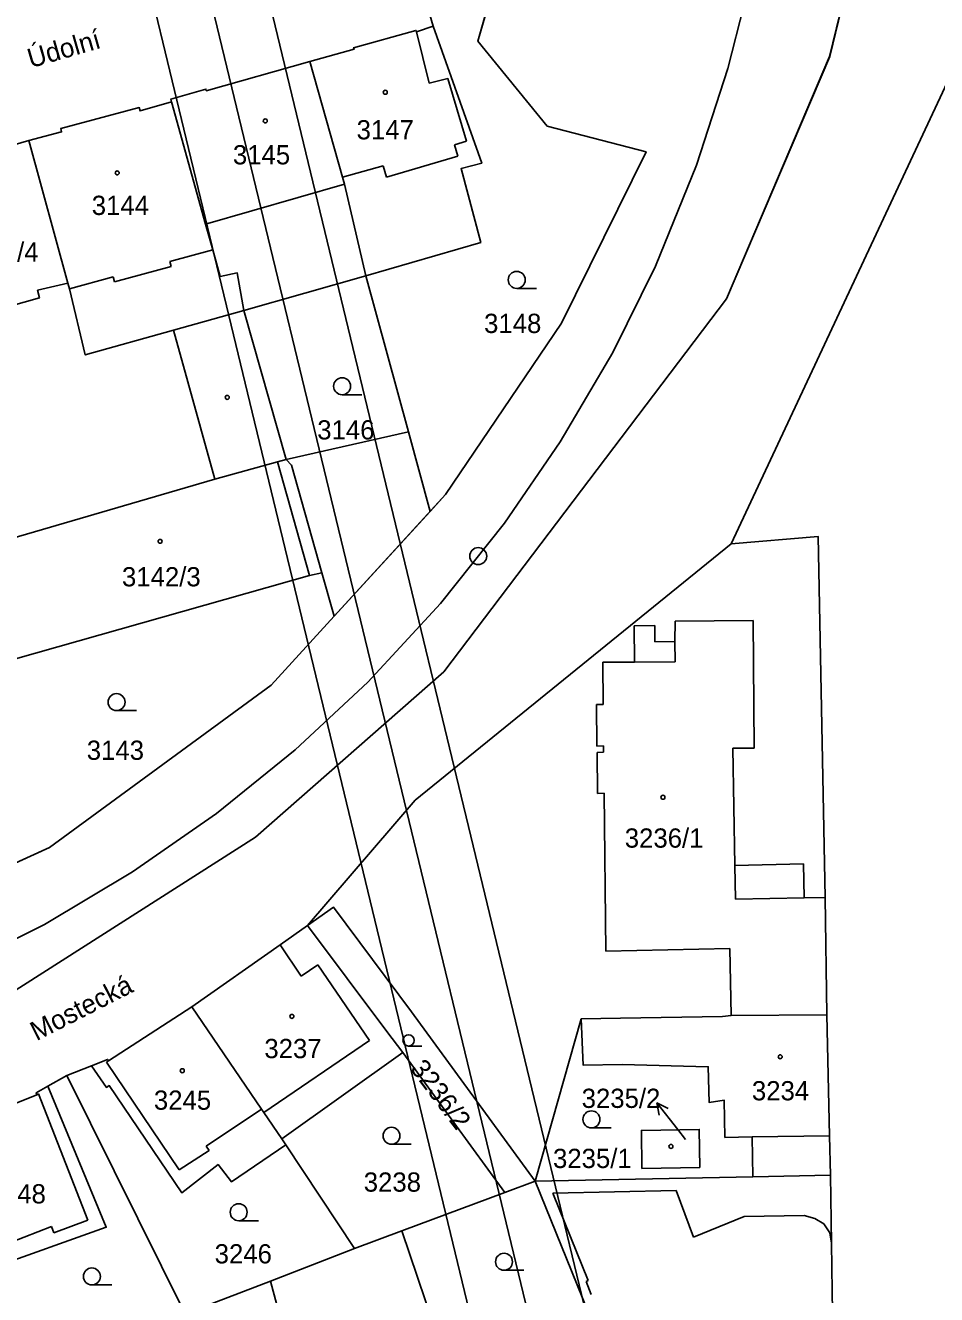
# Model space of a CAD drawing. Extents: x -738085 to -734306, y -1122197 to -1119753.
# Drawn here: x -734521 to -734440.5, y -1120242.7 to -1120130.5 of the extents above; entities that cross this region are included whole.
import ezdxf

# ---------------------------------------------------------------- set-up
doc = ezdxf.new("R2010")
doc.units = 0
for name, color, linetype in [('Hranice parcel', 7, 'Continuous'), ('Parcelní čísla', 7, 'Continuous'), ('Pop  PČ popisy', 7, 'Continuous'), ('SŽDC', 7, 'Continuous'), ('Vnitřní kresba', 7, 'Continuous'), ('Vrstva 1', 7, 'Continuous'), ('Vrstva 53', 7, 'Continuous'), ('Vrstva 7', 7, 'Continuous'), ('Značky budov', 7, 'Continuous'), ('Značky kultur', 7, 'Continuous')]:
    doc.layers.add(name, color=color, linetype=linetype)

msp = doc.modelspace()

# ---------------------------------------------------------------- linework, layer by layer
at = {"layer": 'Hranice parcel'}
for p, q in [((-734439.36, -1120135.08), (-734458.68, -1120176.34)), ((-734530.15, -1120143.44), (-734520.74, -1120140.71)), ((-734520.74, -1120140.71), (-734517.27, -1120153.31)), ((-734501.73, -1120155.71), (-734490.95, -1120152.67)), ((-734493.74, -1120182.73), (-734485.26, -1120173.47)), ((-734493.74, -1120182.73), (-734494.83, -1120178.89)), ((-734471.92, -1120218.33), (-734475.99, -1120232.66)), ((-734498.39, -1120228.91), (-734487.7, -1120221.3)), ((-734487.7, -1120221.3), (-734478.67, -1120233.66)), ((-734515.18, -1120222.46), (-734517.37, -1120223.32)), ((-734519.05, -1120224.27), (-734517.37, -1120223.32)), ((-734517.37, -1120223.32), (-734506.91, -1120244.39)), ((-734498.39, -1120228.91), (-734498.03, -1120229.45)), ((-734498.03, -1120229.45), (-734491.96, -1120238.61)), ((-734456.77, -1120232.27), (-734475.99, -1120232.66)), ((-734449.91, -1120232.13), (-734456.77, -1120232.27)), ((-734487.77, -1120237.05), (-734478.67, -1120233.66)), ((-734478.67, -1120233.66), (-734475.99, -1120232.66)), ((-734475.99, -1120232.66), (-734470.79, -1120245.51)), ((-734491.96, -1120238.61), (-734487.77, -1120237.05)), ((-734487.77, -1120237.05), (-734483.64, -1120249.33)), ((-734491.96, -1120238.61), (-734499.39, -1120241.49)), ((-734499.39, -1120241.49), (-734506.91, -1120244.39)), ((-734499.39, -1120241.49), (-734495.84, -1120254.63))]:
    msp.add_line(p, q, dxfattribs=at)
for points in [[(-734443.58, -1120106.95), (-734449.99, -1120133.29), (-734459.08, -1120154.68), (-734484.08, -1120187.66), (-734500.69, -1120202.26), (-734522.92, -1120216.44), (-734543.71, -1120224.54), (-734562.36, -1120229.51), (-734589.59, -1120229.56), (-734612.32, -1120225.54), (-734626.24, -1120221.38), (-734644.28, -1120218.16), (-734681.74, -1120210.16)], [(-734485.02, -1120130.59), (-734486.3, -1120126.17), (-734486.35, -1120125.79), (-734485.81, -1120123.35)], [(-734485.26, -1120173.47), (-734483.91, -1120171.99), (-734473.68, -1120156.85), (-734466.2, -1120141.71), (-734474.93, -1120139.44), (-734481.07, -1120131.93), (-734479.71, -1120127.23), (-734479.27, -1120124.78)], [(-734495.9, -1120133.73), (-734492, -1120132.64), (-734492.04, -1120132.5), (-734486.53, -1120130.97), (-734486.49, -1120131.11), (-734485.02, -1120130.59)], [(-734490.95, -1120152.67), (-734480.8, -1120149.72), (-734482.54, -1120143.18), (-734480.72, -1120142.71), (-734485.02, -1120130.59)], [(-734508.13, -1120137.27), (-734508.19, -1120137.06), (-734505.09, -1120136.16), (-734505.05, -1120136.3), (-734495.9, -1120133.73)], [(-734490.95, -1120152.67), (-734492.84, -1120144.55), (-734493.01, -1120143.93), (-734495.9, -1120133.73)], [(-734520.74, -1120140.71), (-734517.83, -1120139.94), (-734517.91, -1120139.64), (-734510.98, -1120137.79), (-734510.9, -1120138.08), (-734508.13, -1120137.27)], [(-734501.73, -1120155.71), (-734502.31, -1120152.4), (-734503.84, -1120152.71), (-734504.48, -1120150.35), (-734505.11, -1120148.08), (-734508.13, -1120137.27)], [(-734517.27, -1120153.31), (-734519.95, -1120153.93), (-734519.79, -1120154.61), (-734523.89, -1120155.76), (-734524.07, -1120155.1), (-734526.69, -1120155.84), (-734530.15, -1120143.44)], [(-734485.26, -1120173.47), (-734487.19, -1120166.43), (-734490.95, -1120152.67)], [(-734501.73, -1120155.71), (-734507.95, -1120157.45), (-734515.75, -1120159.64), (-734517.13, -1120153.82), (-734517.27, -1120153.31)], [(-734494.83, -1120178.89), (-734497.52, -1120169.38), (-734498, -1120168.89), (-734501.73, -1120155.71)], [(-734458.68, -1120176.34), (-734486.59, -1120198.98), (-734496.12, -1120210.08)], [(-734458.68, -1120176.34), (-734451.01, -1120175.68), (-734450.37, -1120207.58), (-734450.23, -1120217.95)], [(-734521.91, -1120186.49), (-734495.93, -1120179.13), (-734494.83, -1120178.89)], [(-734525.37, -1120206.12), (-734518.89, -1120203.17), (-734499.33, -1120188.83), (-734493.74, -1120182.73)], [(-734496.12, -1120210.08), (-734493.8, -1120208.46), (-734486.92, -1120217.7), (-734475.99, -1120232.66)], [(-734496.12, -1120210.08), (-734498.52, -1120211.77), (-734506.33, -1120217.25)], [(-734496.12, -1120210.08), (-734489.09, -1120219.44), (-734487.7, -1120221.3)], [(-734506.33, -1120217.25), (-734513.68, -1120222.04), (-734513.77, -1120221.91), (-734515.18, -1120222.46)], [(-734506.33, -1120217.25), (-734500.16, -1120226.29), (-734499.96, -1120226.59), (-734498.39, -1120228.91)], [(-734450.23, -1120217.95), (-734458.67, -1120218.03), (-734459.44, -1120218.11), (-734468.46, -1120218.27), (-734471.92, -1120218.33)], [(-734450.23, -1120217.95), (-734449.99, -1120228.65), (-734449.91, -1120232.13)], [(-734471.92, -1120218.33), (-734471.75, -1120222.42), (-734468.3, -1120222.35), (-734460.7, -1120222.55), (-734460.64, -1120225.71), (-734459.3, -1120225.51), (-734459.24, -1120228.79), (-734456.84, -1120228.75), (-734456.77, -1120232.27)], [(-734515.18, -1120222.46), (-734513.88, -1120224.38), (-734513.63, -1120224.21), (-734507.21, -1120233.7), (-734504.01, -1120231.2), (-734502.82, -1120232.73), (-734498.03, -1120229.45)], [(-734528.66, -1120228.48), (-734520.03, -1120225.02), (-734520.09, -1120224.86), (-734519.05, -1120224.27)], [(-734524.13, -1120240.37), (-734513.89, -1120236.74), (-734519.05, -1120224.27)], [(-734461.44, -1120231.44), (-734466.56, -1120231.54), (-734466.61, -1120228.18), (-734461.5, -1120228.09), (-734461.44, -1120231.44)], [(-734449.65, -1120249.47), (-734449.76, -1120242.38), (-734449.82, -1120238.13), (-734449.91, -1120232.13)]]:
    msp.add_lwpolyline(points, dxfattribs=at)
at = {"layer": 'Pop  PČ popisy'}
for p, q in [((-734463.4, -1120228.11), (-734465.25, -1120225.75)), ((-734465.25, -1120225.75), (-734464.24, -1120226.23)), ((-734465.25, -1120225.75), (-734465.03, -1120226.84)), ((-734462.71, -1120228.98), (-734463.4, -1120228.11))]:
    msp.add_line(p, q, dxfattribs=at)
at = {"layer": 'SŽDC'}
for p, q in [((-734449.99, -1120133.29), (-734443.58, -1120106.95)), ((-734479.71, -1120127.23), (-734481.07, -1120131.93)), ((-734481.07, -1120131.93), (-734474.93, -1120139.44)), ((-734459.08, -1120154.68), (-734449.99, -1120133.29)), ((-734474.93, -1120139.44), (-734466.2, -1120141.71)), ((-734466.2, -1120141.71), (-734473.68, -1120156.85)), ((-734484.08, -1120187.66), (-734459.08, -1120154.68)), ((-734473.68, -1120156.85), (-734483.91, -1120171.99)), ((-734483.91, -1120171.99), (-734485.26, -1120173.47)), ((-734485.26, -1120173.47), (-734493.74, -1120182.73)), ((-734493.74, -1120182.73), (-734499.33, -1120188.83)), ((-734500.69, -1120202.26), (-734484.08, -1120187.66)), ((-734499.33, -1120188.83), (-734518.89, -1120203.17)), ((-734522.92, -1120216.44), (-734500.69, -1120202.26)), ((-734518.89, -1120203.17), (-734525.37, -1120206.12))]:
    msp.add_line(p, q, dxfattribs=at)
at = {"layer": 'Vnitřní kresba'}
for p, q in [((-734486.49, -1120131.11), (-734485.37, -1120135.63)), ((-734485.37, -1120135.63), (-734483.7, -1120135.21)), ((-734483.7, -1120135.21), (-734482.07, -1120140.75)), ((-734483.13, -1120141.07), (-734482.07, -1120140.75)), ((-734483.13, -1120141.07), (-734482.83, -1120142.08)), ((-734489.12, -1120143.94), (-734482.83, -1120142.08)), ((-734493.01, -1120143.93), (-734489.42, -1120142.94)), ((-734489.42, -1120142.94), (-734489.12, -1120143.94)), ((-734505.11, -1120148.08), (-734492.84, -1120144.55)), ((-734508.28, -1120151.4), (-734504.48, -1120150.35)), ((-734513.15, -1120153.18), (-734508.16, -1120151.83)), ((-734508.28, -1120151.4), (-734508.16, -1120151.83)), ((-734517.13, -1120153.82), (-734513.27, -1120152.75)), ((-734513.27, -1120152.75), (-734513.15, -1120153.18)), ((-734507.95, -1120157.45), (-734504.31, -1120170.63)), ((-734498, -1120168.89), (-734487.19, -1120166.43)), ((-734504.31, -1120170.63), (-734498.76, -1120169.1)), ((-734498.76, -1120169.1), (-734498, -1120168.89)), ((-734498.76, -1120169.1), (-734495.93, -1120179.13)), ((-734524.76, -1120176.61), (-734504.31, -1120170.63)), ((-734463.66, -1120184.98), (-734463.64, -1120183.18)), ((-734463.64, -1120183.18), (-734456.74, -1120183.13)), ((-734456.74, -1120183.13), (-734456.65, -1120194.4)), ((-734467.24, -1120183.58), (-734465.44, -1120183.57)), ((-734467.24, -1120183.58), (-734467.22, -1120186.81)), ((-734465.44, -1120183.57), (-734465.43, -1120185)), ((-734465.43, -1120185), (-734463.66, -1120184.98)), ((-734463.66, -1120184.98), (-734463.62, -1120186.78)), ((-734470.03, -1120186.8), (-734467.22, -1120186.81)), ((-734470.03, -1120186.8), (-734469.99, -1120190.53)), ((-734467.22, -1120186.81), (-734463.62, -1120186.78)), ((-734470.59, -1120190.54), (-734469.99, -1120190.53)), ((-734470.59, -1120190.54), (-734470.55, -1120194.21)), ((-734470.55, -1120194.21), (-734469.95, -1120194.2)), ((-734469.95, -1120194.48), (-734469.95, -1120194.2)), ((-734469.95, -1120194.76), (-734469.95, -1120194.48)), ((-734458.53, -1120194.41), (-734456.65, -1120194.4)), ((-734458.53, -1120194.41), (-734458.35, -1120204.76)), ((-734470.53, -1120194.77), (-734469.95, -1120194.76)), ((-734470.53, -1120194.77), (-734470.49, -1120198.39)), ((-734470.49, -1120198.39), (-734469.91, -1120198.38)), ((-734469.91, -1120198.38), (-734469.76, -1120212.33)), ((-734458.35, -1120204.76), (-734452.3, -1120204.63)), ((-734458.35, -1120204.76), (-734458.29, -1120207.74)), ((-734452.3, -1120204.63), (-734452.24, -1120207.62)), ((-734458.29, -1120207.74), (-734452.24, -1120207.62)), ((-734452.24, -1120207.62), (-734450.37, -1120207.58)), ((-734498.52, -1120211.77), (-734496.68, -1120214.56)), ((-734469.76, -1120212.33), (-734458.79, -1120212.1)), ((-734458.79, -1120212.1), (-734458.67, -1120218.03)), ((-734496.68, -1120214.56), (-734495.19, -1120213.54)), ((-734495.19, -1120213.54), (-734490.63, -1120220.23)), ((-734499.96, -1120226.59), (-734490.63, -1120220.23)), ((-734513.86, -1120222.16), (-734513.68, -1120222.04)), ((-734513.86, -1120222.16), (-734507.46, -1120231.66)), ((-734520.03, -1120225.02), (-734519.86, -1120224.93)), ((-734519.86, -1120224.93), (-734515.52, -1120236.1)), ((-734505.06, -1120229.57), (-734500.16, -1120226.29)), ((-734456.84, -1120228.75), (-734449.99, -1120228.65)), ((-734507.46, -1120231.66), (-734504.81, -1120229.96)), ((-734505.06, -1120229.57), (-734504.81, -1120229.96)), ((-734474.45, -1120233.72), (-734463.55, -1120233.49)), ((-734474.45, -1120233.72), (-734471.31, -1120241.45)), ((-734463.55, -1120233.49), (-734462, -1120237.61)), ((-734462, -1120237.61), (-734457.54, -1120235.79)), ((-734457.54, -1120235.79), (-734452.23, -1120235.71)), ((-734452.23, -1120235.71), (-734451.29, -1120235.95)), ((-734451.29, -1120235.95), (-734450.49, -1120236.44)), ((-734524.66, -1120238.96), (-734518.72, -1120236.68)), ((-734518.72, -1120236.68), (-734518.51, -1120237.23)), ((-734518.51, -1120237.23), (-734515.52, -1120236.1)), ((-734450.49, -1120236.44), (-734449.98, -1120237.23)), ((-734449.98, -1120237.23), (-734449.82, -1120238.13)), ((-734471.5, -1120241.52), (-734471.31, -1120241.45)), ((-734471.5, -1120241.52), (-734471.04, -1120242.69))]:
    msp.add_line(p, q, dxfattribs=at)
at = {"layer": 'Vrstva 1'}
for points in [[(-734534.27, -1119984.39), (-735554.91, -1120230.88), (-735485.2, -1120519.57), (-734464.55, -1120273.08)], [(-734470.58, -1120269.4), (-735481.51, -1120513.53), (-735548.88, -1120234.56), (-734537.95, -1119990.43)], [(-734541.63, -1119996.45), (-735348.44, -1120191.3), (-735283.42, -1120460.56), (-734476.61, -1120265.71)]]:
    msp.add_lwpolyline(points, close=True, dxfattribs=at)
msp.add_lwpolyline([(-734457.52, -1120128.68), (-734458.98, -1120134.34), (-734461.74, -1120142.87), (-734465.37, -1120151.8), (-734469.15, -1120159.42), (-734473.78, -1120167.32), (-734478.71, -1120174.52), (-734484.35, -1120181.61), (-734490.79, -1120188.56), (-734497.21, -1120194.54), (-734504.15, -1120200.17), (-734511.58, -1120205.34), (-734519.33, -1120209.98), (-734527.98, -1120214.28), (-734537.01, -1120217.94), (-734545.52, -1120220.65), (-734554.88, -1120222.87), (-734563.63, -1120224.26), (-734570.58, -1120224.9), (-734571.05, -1120224.92), (-734578.72, -1120225.21)], dxfattribs=at)
at = {"layer": 'Vrstva 53'}
for points in [[(-734443.58, -1120106.95), (-734449.97, -1120133.28), (-734459.08, -1120154.68), (-734484.08, -1120187.66), (-734500.69, -1120202.26), (-734522.92, -1120216.44), (-734543.71, -1120224.54), (-734562.36, -1120229.51), (-734589.59, -1120229.56)], [(-734585.49, -1120220.06), (-734570.35, -1120219.16), (-734562.37, -1120218.68), (-734542.11, -1120213.74), (-734518.89, -1120203.17), (-734499.33, -1120188.83), (-734493.74, -1120182.73), (-734483.91, -1120171.99), (-734473.68, -1120156.85), (-734466.2, -1120141.71), (-734474.93, -1120139.44), (-734481.07, -1120131.93), (-734479.71, -1120127.23)]]:
    msp.add_lwpolyline(points, dxfattribs=at)
at = {"layer": 'Vrstva 7'}
msp.add_circle((-734481.03, -1120177.43), 0.75, dxfattribs=at)
at = {"layer": 'Značky budov'}
for centre in [(-734489.24, -1120136.44), (-734499.84, -1120138.97), (-734512.92, -1120143.56), (-734503.2, -1120163.4), (-734509.13, -1120176.12), (-734464.71, -1120198.74), (-734497.49, -1120218.1), (-734454.35, -1120221.67), (-734507.17, -1120222.9), (-734464, -1120229.59)]:
    msp.add_circle(centre, 0.175, dxfattribs=at)
at = {"layer": 'Značky kultur'}
for p, q in [((-734477.63, -1120153.77), (-734475.88, -1120153.77)), ((-734493.05, -1120163.17), (-734491.3, -1120163.17)), ((-734512.98, -1120191.08), (-734511.23, -1120191.08)), ((-734487.18, -1120220.72), (-734486, -1120220.72)), ((-734471.03, -1120227.95), (-734469.28, -1120227.95)), ((-734488.69, -1120229.4), (-734486.94, -1120229.4)), ((-734502.19, -1120236.16), (-734500.44, -1120236.16)), ((-734478.75, -1120240.53), (-734477, -1120240.53)), ((-734515.16, -1120241.83), (-734513.41, -1120241.83))]:
    msp.add_line(p, q, dxfattribs=at)
for centre, radius in [((-734477.63, -1120153.02), 0.75), ((-734493.05, -1120162.42), 0.75), ((-734512.98, -1120190.33), 0.75), ((-734487.18, -1120220.22), 0.502), ((-734471.03, -1120227.2), 0.75), ((-734488.69, -1120228.65), 0.75), ((-734502.19, -1120235.41), 0.75), ((-734478.75, -1120239.78), 0.75), ((-734515.16, -1120241.08), 0.75)]:
    msp.add_circle(centre, radius, dxfattribs=at)

# ---------------------------------------------------------------- texts
at = {"layer": 'Parcelní čísla'}
for s, p in [('3147', (-734491.77, -1120140.6)), ('3145', (-734502.7, -1120142.81)), ('3144', (-734515.17, -1120147.28)), ('3142/4', (-734526.82, -1120151.4)), ('3148', (-734480.51, -1120157.71)), ('3146', (-734495.25, -1120167.12)), ('3142/3', (-734512.5, -1120180.1)), ('3143', (-734515.61, -1120195.43)), ('3236/1', (-734468.08, -1120203.19)), ('3237', (-734499.92, -1120221.79)), ('3245', (-734509.68, -1120226.35)), ('3235/2', (-734471.89, -1120226.19)), ('3234', (-734456.85, -1120225.52)), ('3235/1', (-734474.42, -1120231.5)), ('3238', (-734491.14, -1120233.59)), ('3248', (-734524.28, -1120234.63)), ('3246', (-734504.31, -1120239.93))]:
    msp.add_text(s, height=1.7, dxfattribs=at).set_placement(p)
msp.add_text('3236/2', height=1.7, rotation=307, dxfattribs=at).set_placement((-734487.1, -1120222.72))
at = {"layer": 'Pop  PČ popisy'}
for s, rotation, p in [('Údolní', 16, (-734520.56, -1120134.31)), ('Mostecká', 27, (-734520.05, -1120220.3))]:
    msp.add_text(s, height=1.7, rotation=rotation, dxfattribs=at).set_placement(p)

doc.saveas('drawing.dxf')
